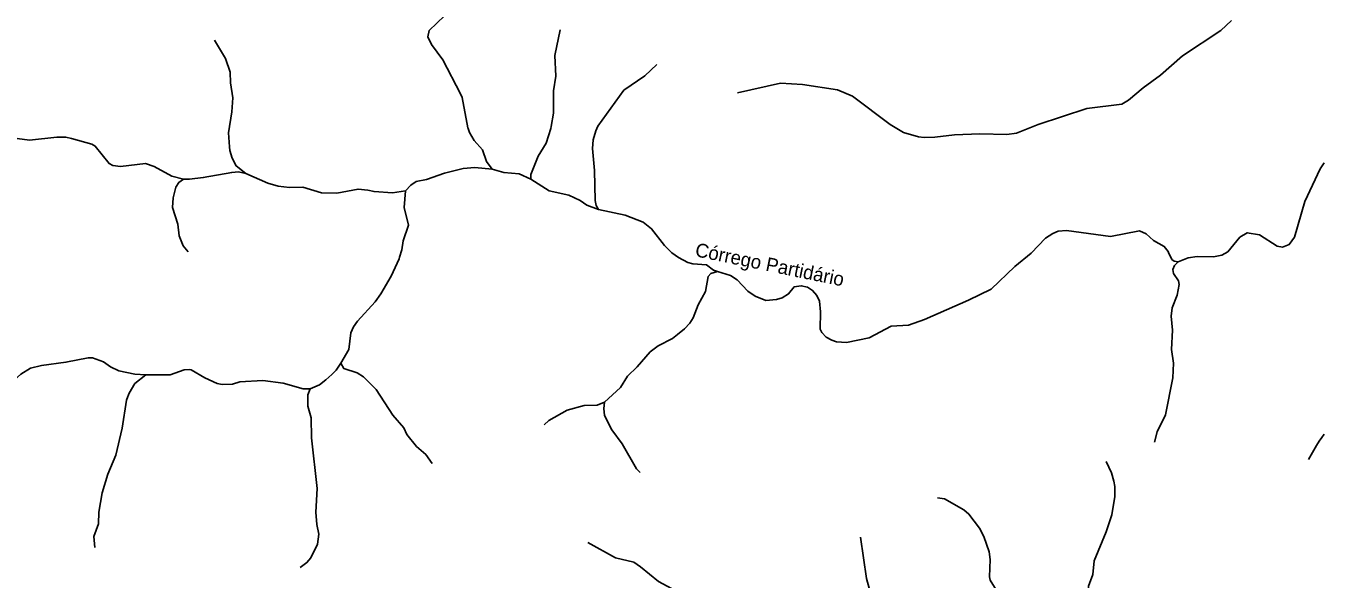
# Model space of a CAD drawing. Extents: x 473.9 to 500, y 7733.1 to 7760.8.
# Drawn here: x 492.5 to 500, y 7745.21 to 7748.41 of the extents above; entities that cross this region are included whole.
import ezdxf
from ezdxf.enums import TextEntityAlignment as Align

# ---------------------------------------------------------------- set-up
doc = ezdxf.new("R2010")
doc.units = 0
doc.header["$LTSCALE"] = 0.032
doc.layers.add('61', color=7, linetype='Continuous')
doc.layers.add('7', color=7, linetype='Continuous', lineweight=25)

msp = doc.modelspace()

# ---------------------------------------------------------------- linework, layer by layer
at = {"layer": '7'}
for points in [[(495.0964, 7748.8813), (495.0191, 7748.7727), (495.0098, 7748.7448), (495.0048, 7748.6765), (494.9833, 7748.5909), (494.9397, 7748.4943), (494.9165, 7748.4644), (494.8281, 7748.3809), (494.8196, 7748.3438), (494.8415, 7748.3001), (494.9062, 7748.2108), (495.0091, 7748.0145), (495.0184, 7747.9927), (495.0514, 7747.817), (495.0521, 7747.8135), (495.0609, 7747.7906), (495.0881, 7747.7449), (495.1348, 7747.6909), (495.1595, 7747.6239), (495.1916, 7747.5788)], [(496.6095, 7748.0194), (496.8583, 7748.0758), (496.985, 7748.0679), (497.1886, 7748.0366), (497.2753, 7748), (497.493, 7747.8379), (497.5685, 7747.7911), (497.6553, 7747.7656), (497.6882, 7747.7616), (497.7499, 7747.7631), (497.8649, 7747.7775), (498.0097, 7747.7832), (498.1667, 7747.7784), (498.222, 7747.7864), (498.3484, 7747.836), (498.6294, 7747.9303), (498.8316, 7747.9542), (498.8705, 7747.9775), (498.954, 7748.0481), (499.0553, 7748.1221), (499.182, 7748.233), (499.4041, 7748.381), (499.4649, 7748.4372)], [(495.5846, 7748.3845), (495.554, 7748.235), (495.5589, 7748.1156), (495.5457, 7748.0323), (495.5453, 7747.9026), (495.5329, 7747.8256), (495.5309, 7747.8132), (495.5035, 7747.7292), (495.458, 7747.654), (495.4156, 7747.5473), (495.4142, 7747.5216)], [(493.5865, 7748.3241), (493.6508, 7748.2185), (493.678, 7748.1396), (493.6799, 7748.0769), (493.6917, 7747.9919), (493.6868, 7747.9106), (493.6676, 7747.7883), (493.6739, 7747.7076), (493.6756, 7747.6858), (493.6891, 7747.6415), (493.7125, 7747.5981), (493.7686, 7747.5539)], [(496.1435, 7748.1844), (496.0748, 7748.1177), (495.9531, 7748.0362), (495.8029, 7747.8275), (495.7902, 7747.8011), (495.7748, 7747.7476), (495.7723, 7747.6983), (495.7826, 7747.5714), (495.7875, 7747.3972), (495.7936, 7747.3693), (495.807, 7747.3465)], [(492.4457, 7747.7561), (492.5181, 7747.747), (492.6746, 7747.7647), (492.7266, 7747.7647), (492.7605, 7747.7553), (492.877, 7747.723), (492.8969, 7747.7124), (492.9769, 7747.6113), (492.9991, 7747.5996), (493.0428, 7747.5948), (493.1871, 7747.6114), (493.2375, 7747.5933), (493.3391, 7747.5393), (493.4074, 7747.522)], [(494.6915, 7747.4535), (494.7221, 7747.4869), (494.7528, 7747.508), (494.8116, 7747.5195), (494.917, 7747.5555), (495.0238, 7747.5819), (495.0908, 7747.5891), (495.1916, 7747.5788)], [(499.1565, 7747.0438), (499.2142, 7747.0671), (499.266, 7747.0743), (499.3612, 7747.0729), (499.4095, 7747.0813), (499.4432, 7747.1006), (499.5133, 7747.1858), (499.5566, 7747.2114), (499.6267, 7747.1985), (499.7289, 7747.1337), (499.7592, 7747.129), (499.7987, 7747.1434), (499.8302, 7747.1861), (499.8888, 7747.3918), (499.9781, 7747.5813), (500, 7747.6158)], [(493.4336, 7747.1009), (493.4053, 7747.1356), (493.3823, 7747.1932), (493.3742, 7747.2609), (493.3437, 7747.3568), (493.3469, 7747.4125), (493.3626, 7747.4754), (493.3796, 7747.5023), (493.4074, 7747.522)], [(493.4074, 7747.522), (493.4418, 7747.5202), (493.5212, 7747.53), (493.6861, 7747.5601), (493.7256, 7747.5634), (493.7686, 7747.5539)], [(493.7686, 7747.5539), (493.8955, 7747.4976), (493.9552, 7747.4802), (494.0208, 7747.4729), (494.0973, 7747.4744), (494.2058, 7747.4429), (494.2933, 7747.4409), (494.417, 7747.4633), (494.4729, 7747.4577), (494.5091, 7747.449), (494.6155, 7747.4425), (494.6915, 7747.4535)], [(495.1916, 7747.5788), (495.259, 7747.5604), (495.3474, 7747.5516), (495.4142, 7747.5216)], [(495.4142, 7747.5216), (495.5206, 7747.4531), (495.6342, 7747.4293), (495.7002, 7747.3971), (495.738, 7747.3717), (495.807, 7747.3465)], [(494.3166, 7746.4575), (494.3634, 7746.5361), (494.3745, 7746.6331), (494.3901, 7746.6681), (494.4131, 7746.7013), (494.5157, 7746.8127), (494.5483, 7746.8581), (494.6074, 7746.96), (494.6533, 7747.0611), (494.6562, 7747.0703), (494.6696, 7747.1133), (494.6778, 7747.1647), (494.7074, 7747.2545), (494.6827, 7747.3567), (494.6915, 7747.4535)], [(495.807, 7747.3465), (495.9603, 7747.3134), (496.0639, 7747.2729), (496.1135, 7747.2342), (496.1878, 7747.1386), (496.2298, 7747.0955), (496.2682, 7747.0681), (496.3223, 7747.0402), (496.3512, 7747.032), (496.4308, 7747.0269), (496.471, 7746.9949), (496.494, 7746.9868)], [(496.494, 7746.9868), (496.5701, 7746.9645), (496.6087, 7746.9394), (496.669, 7746.8744), (496.7117, 7746.8447), (496.7733, 7746.8203), (496.835, 7746.8259), (496.8674, 7746.8349), (496.9052, 7746.8576), (496.9366, 7746.8988), (496.9786, 7746.9053), (497.0142, 7746.8979), (497.0433, 7746.8777), (497.0681, 7746.8487), (497.084, 7746.8167), (497.0903, 7746.7542), (497.088, 7746.6546), (497.0978, 7746.6348), (497.1231, 7746.6085), (497.1542, 7746.5909), (497.1813, 7746.582), (497.2395, 7746.5773), (497.3701, 7746.6037), (497.4985, 7746.6718), (497.5982, 7746.6772), (497.6905, 7746.7096), (497.9455, 7746.8217), (498.0756, 7746.8858), (498.2128, 7747.0166), (498.308, 7747.0926), (498.3906, 7747.1799), (498.432, 7747.2076), (498.4639, 7747.2203), (498.5116, 7747.2243), (498.766, 7747.1899), (498.9333, 7747.2219), (498.9718, 7747.206), (499.014, 7747.1662), (499.0766, 7747.1327), (499.0988, 7747.104), (499.1019, 7747.0974), (499.1208, 7747.0574), (499.134, 7747.0481), (499.1565, 7747.0438)], [(495.8417, 7746.2317), (495.9333, 7746.3175), (495.9741, 7746.3822), (496.0302, 7746.4367), (496.1047, 7746.5225), (496.1504, 7746.5576), (496.2335, 7746.5999), (496.2635, 7746.624), (496.3025, 7746.6553), (496.3342, 7746.6884), (496.3537, 7746.7195), (496.383, 7746.7958), (496.4247, 7746.8728), (496.4399, 7746.9583), (496.4553, 7746.9759), (496.494, 7746.9868)], [(499.0208, 7746.0005), (499.0352, 7746.0611), (499.0831, 7746.159), (499.1253, 7746.3735), (499.1293, 7746.457), (499.1181, 7746.5358), (499.1237, 7746.6481), (499.1165, 7746.7299), (499.123, 7746.7776), (499.1503, 7746.8514), (499.163, 7746.9115), (499.1596, 7746.9343), (499.1301, 7746.9758), (499.1255, 7746.9984), (499.1252, 7746.9996), (499.135, 7747.023), (499.1565, 7747.0438)], [(492.0417, 7746.0779), (492.1297, 7746.1018), (492.2309, 7746.1456), (492.2541, 7746.1653), (492.3629, 7746.2896), (492.4114, 7746.345), (492.4672, 7746.3936), (492.5235, 7746.4289), (492.5864, 7746.4441), (492.7282, 7746.4627), (492.8558, 7746.4882), (492.8822, 7746.4882), (492.9453, 7746.4646), (492.9856, 7746.4371), (493.0345, 7746.4142), (493.1262, 7746.3936), (493.1905, 7746.39)], [(494.1401, 7746.3103), (494.1929, 7746.3332), (494.2306, 7746.3605), (494.2641, 7746.3927), (494.2906, 7746.4182), (494.3166, 7746.4575)], [(494.8448, 7745.8775), (494.8078, 7745.9291), (494.7539, 7745.9769), (494.6991, 7746.0451), (494.6816, 7746.0844), (494.6172, 7746.1569), (494.5209, 7746.3052), (494.4487, 7746.379), (494.411, 7746.4011), (494.3336, 7746.427), (494.3166, 7746.4575)], [(492.8943, 7745.3916), (492.8897, 7745.457), (492.9153, 7745.5287), (492.9187, 7745.5971), (492.938, 7745.7092), (492.9706, 7745.8162), (493.0157, 7745.927), (493.0533, 7746.0826), (493.0784, 7746.2438), (493.0794, 7746.2504), (493.0924, 7746.2841), (493.1266, 7746.3394), (493.1905, 7746.39)], [(493.1905, 7746.39), (493.3305, 7746.3912), (493.411, 7746.4185), (493.4409, 7746.4208), (493.4517, 7746.4195), (493.5315, 7746.3735), (493.6027, 7746.3402), (493.6315, 7746.3344), (493.6913, 7746.3367), (493.7336, 7746.3492), (493.8661, 7746.3575), (493.9842, 7746.3414), (494.0986, 7746.3095), (494.1401, 7746.3103)], [(494.0809, 7745.2763), (494.1211, 7745.3054), (494.1436, 7745.3319), (494.1828, 7745.4113), (494.1903, 7745.4697), (494.1775, 7745.5261), (494.1719, 7745.5977), (494.1791, 7745.7328), (494.1471, 7746.0258), (494.1453, 7746.1421), (494.1262, 7746.2086), (494.127, 7746.2741), (494.1401, 7746.3103)], [(495.4916, 7746.1023), (495.5182, 7746.1265), (495.6244, 7746.1867), (495.7227, 7746.2131), (495.7992, 7746.2154), (495.8417, 7746.2317)], [(496.0467, 7745.8265), (496.0251, 7745.8468), (495.943, 7745.9911), (495.8841, 7746.0729), (495.8404, 7746.1559), (495.8371, 7746.1954), (495.8417, 7746.2317)], [(499.9106, 7745.9004), (499.9342, 7745.9411), (499.9557, 7745.9829), (499.9722, 7746.0066), (499.987, 7746.028), (500, 7746.0484)], [(498.741, 7745.8896), (498.7715, 7745.8231), (498.7848, 7745.7768), (498.7909, 7745.7442), (498.7909, 7745.6881), (498.7725, 7745.5809), (498.741, 7745.4838), (498.6718, 7745.3155), (498.6628, 7745.2366), (498.6378, 7745.1688), (498.6434, 7745.0688), (498.6358, 7745.0043)], [(497.7661, 7745.6796), (497.8066, 7745.6735), (497.9181, 7745.6109), (497.9471, 7745.5857), (498.0085, 7745.5035), (498.0327, 7745.4566), (498.0646, 7745.3671), (498.0709, 7745.3229), (498.0654, 7745.224), (498.0697, 7745.2044), (498.115, 7745.1324), (498.1628, 7745.0297), (498.1897, 7745.0029)], [(495.744, 7745.4219), (495.9039, 7745.3332), (496.0106, 7745.3071), (496.0494, 7745.2818), (496.1528, 7745.1957), (496.2285, 7745.1548), (496.2851, 7745.1339)], [(497.3215, 7745.4526), (497.3558, 7745.2131), (497.3799, 7745.1233), (497.4205, 7744.8774), (497.4292, 7744.8521), (497.4487, 7744.828)]]:
    msp.add_lwpolyline(points, dxfattribs=at)

# ---------------------------------------------------------------- texts
at = {"layer": '61'}
msp.add_text('Córrego Partidário', height=0.08, rotation=348.446, dxfattribs=at).set_placement((496.7883, 7746.9888), align=Align.CENTER)

doc.saveas('drawing.dxf')
